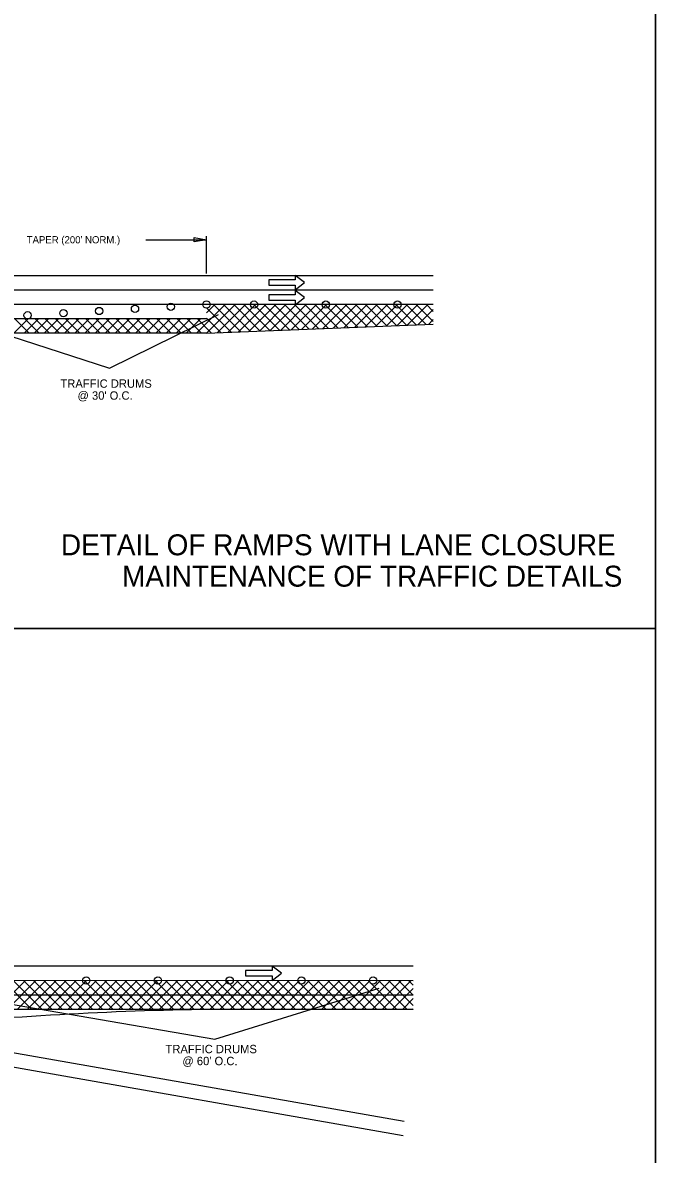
# Model space of a CAD drawing. Extents: x -100 to 745, y -1581 to -107.
# Drawn here: x 292.5 to 345.4, y -1294.6 to -1199.9 of the extents above; entities that cross this region are included whole.
import ezdxf

# ---------------------------------------------------------------- set-up
doc = ezdxf.new("R2010")
doc.units = 0
for name, color, linetype in [('Default', 7, 'Continuous'), ('R_Contour Annot', 7, 'Continuous'), ('R_Draft', 7, 'Continuous'), ('R_Drive', 7, 'Continuous'), ('R_Erosion', 7, 'Continuous'), ('R_Exist Surface', 7, 'Continuous'), ('R_MOT', 7, 'Continuous')]:
    doc.layers.add(name, color=color, linetype=linetype)

msp = doc.modelspace()

# ---------------------------------------------------------------- linework, layer by layer
at = {"layer": 'Default'}
for points in [[(315.278, -1222.246), (316.056, -1221.646), (315.278, -1221.046), (315.278, -1221.421), (313.071, -1221.421), (313.071, -1221.871), (315.278, -1221.871)], [(315.278, -1223.502), (316.056, -1222.902), (315.278, -1222.302), (315.278, -1222.677), (313.071, -1222.677), (313.071, -1223.127), (315.278, -1223.127)], [(313.328, -1280.021), (314.107, -1279.421), (313.328, -1278.821), (313.328, -1279.196), (311.121, -1279.196), (311.121, -1279.646), (313.328, -1279.646)]]:
    msp.add_lwpolyline(points, close=True, dxfattribs=at)
at = {"layer": 'R_Contour Annot'}
for points in [[(175.406, -1140.582), (345.406, -1140.582), (345.406, -1250.582), (175.406, -1250.582)], [(175.406, -1250.582), (345.406, -1250.582), (345.406, -1360.582), (175.406, -1360.582)]]:
    msp.add_lwpolyline(points, close=True, dxfattribs=at)
at = {"layer": 'R_Draft'}
for p, q in [((326.815, -1221.09), (196.834, -1221.09)), ((326.815, -1222.29), (196.834, -1222.29)), ((326.815, -1223.49), (196.834, -1223.49)), ((307.002, -1225.89), (309.404, -1223.488)), ((307.85, -1225.89), (310.252, -1223.488)), ((307.851, -1223.763), (309.896, -1225.808)), ((307.852, -1224.191), (308.555, -1223.488)), ((308.424, -1223.488), (310.712, -1225.776)), ((308.734, -1225.855), (311.101, -1223.488)), ((309.273, -1223.488), (311.528, -1225.743)), ((309.618, -1225.819), (311.949, -1223.488)), ((310.121, -1223.488), (312.344, -1225.71)), ((310.502, -1225.784), (312.797, -1223.489)), ((310.97, -1223.488), (313.159, -1225.678)), ((311.386, -1225.749), (313.646, -1223.489)), ((311.819, -1223.488), (313.975, -1225.645)), ((312.27, -1225.713), (314.494, -1223.489)), ((312.667, -1223.489), (314.791, -1225.612)), ((313.154, -1225.678), (315.343, -1223.489)), ((313.516, -1223.489), (315.607, -1225.58)), ((314.037, -1225.643), (316.191, -1223.489)), ((314.365, -1223.489), (316.423, -1225.547)), ((314.921, -1225.607), (317.04, -1223.489)), ((315.213, -1223.489), (317.239, -1225.515)), ((315.805, -1225.572), (317.888, -1223.489)), ((316.062, -1223.489), (318.055, -1225.482)), ((316.689, -1225.537), (318.737, -1223.489)), ((316.91, -1223.489), (318.871, -1225.449)), ((317.573, -1225.501), (319.585, -1223.489)), ((317.759, -1223.489), (319.687, -1225.417)), ((318.457, -1225.466), (320.433, -1223.489)), ((318.608, -1223.489), (320.502, -1225.384)), ((319.341, -1225.43), (321.282, -1223.489)), ((319.456, -1223.489), (321.318, -1225.351)), ((320.225, -1225.395), (322.13, -1223.489)), ((320.305, -1223.489), (322.134, -1225.319)), ((321.109, -1225.36), (322.979, -1223.49)), ((321.153, -1223.489), (322.95, -1225.286)), ((321.992, -1225.324), (323.827, -1223.49)), ((322.002, -1223.489), (323.766, -1225.253)), ((322.851, -1223.49), (324.582, -1225.221)), ((322.876, -1225.289), (324.676, -1223.49)), ((323.699, -1223.49), (325.398, -1225.188)), ((323.76, -1225.254), (325.524, -1223.49)), ((324.548, -1223.49), (326.214, -1225.156)), ((324.644, -1225.218), (326.373, -1223.49)), ((325.396, -1223.49), (326.815, -1224.908)), ((325.528, -1225.183), (326.815, -1223.896)), ((326.245, -1223.49), (326.815, -1224.06)), ((307.855, -1224.69), (237.745, -1224.69)), ((291.728, -1225.89), (292.928, -1224.69)), ((291.807, -1224.69), (293.007, -1225.89)), ((292.577, -1225.89), (293.777, -1224.69)), ((292.656, -1224.69), (293.856, -1225.89)), ((293.425, -1225.89), (294.625, -1224.69)), ((293.504, -1224.69), (294.704, -1225.89)), ((294.274, -1225.89), (295.474, -1224.69)), ((294.353, -1224.69), (295.553, -1225.89)), ((295.123, -1225.89), (296.323, -1224.69)), ((295.201, -1224.69), (296.401, -1225.89)), ((295.971, -1225.89), (297.171, -1224.69)), ((296.05, -1224.69), (297.25, -1225.89)), ((296.82, -1225.89), (298.02, -1224.69)), ((296.898, -1224.69), (298.098, -1225.89)), ((297.668, -1225.89), (298.868, -1224.69)), ((297.747, -1224.69), (298.947, -1225.89)), ((298.517, -1225.89), (299.717, -1224.69)), ((298.595, -1224.69), (299.795, -1225.89)), ((299.365, -1225.89), (300.565, -1224.69)), ((299.444, -1224.69), (300.644, -1225.89)), ((300.214, -1225.89), (301.414, -1224.69)), ((300.292, -1224.69), (301.492, -1225.89)), ((301.062, -1225.89), (302.262, -1224.69)), ((301.141, -1224.69), (302.341, -1225.89)), ((301.911, -1225.89), (303.111, -1224.69)), ((301.989, -1224.69), (303.189, -1225.89)), ((302.759, -1225.89), (303.959, -1224.69)), ((302.838, -1224.69), (304.038, -1225.89)), ((303.608, -1225.89), (304.808, -1224.69)), ((303.686, -1224.69), (304.886, -1225.89)), ((304.456, -1225.89), (305.656, -1224.69)), ((304.535, -1224.69), (305.735, -1225.89)), ((305.305, -1225.89), (306.505, -1224.69)), ((305.383, -1224.69), (306.583, -1225.89)), ((306.153, -1225.89), (307.353, -1224.69)), ((306.232, -1224.69), (307.432, -1225.89)), ((307.08, -1224.69), (308.264, -1225.874)), ((307.854, -1224.615), (309.08, -1225.841)), ((326.412, -1225.148), (326.815, -1224.745)), ((307.855, -1225.89), (326.815, -1225.132)), ((307.855, -1225.89), (240.841, -1225.89)), ((325.145, -1278.839), (186.576, -1278.836)), ((325.145, -1280.039), (186.576, -1280.036)), ((290.302, -1282.438), (292.709, -1280.031)), ((290.83, -1280.031), (293.238, -1282.438)), ((291.151, -1282.438), (293.558, -1280.031)), ((291.679, -1280.031), (294.086, -1282.438)), ((291.999, -1282.438), (294.406, -1280.032)), ((292.528, -1280.031), (294.935, -1282.438)), ((292.848, -1282.438), (295.254, -1280.032)), ((293.376, -1280.031), (295.783, -1282.438)), ((293.696, -1282.438), (296.103, -1280.032)), ((294.225, -1280.032), (296.632, -1282.438)), ((294.545, -1282.438), (296.951, -1280.032)), ((295.074, -1280.032), (297.48, -1282.438)), ((295.393, -1282.438), (297.799, -1280.032)), ((295.923, -1280.032), (298.329, -1282.438)), ((296.242, -1282.438), (298.648, -1280.033)), ((296.771, -1280.032), (299.177, -1282.438)), ((297.09, -1282.438), (299.496, -1280.033)), ((297.62, -1280.032), (300.026, -1282.438)), ((297.939, -1282.438), (300.344, -1280.033)), ((298.469, -1280.033), (300.875, -1282.438)), ((298.787, -1282.438), (301.192, -1280.033)), ((299.317, -1280.033), (301.723, -1282.438)), ((299.636, -1282.438), (302.041, -1280.033)), ((300.166, -1280.033), (302.572, -1282.438)), ((300.484, -1282.438), (302.889, -1280.034)), ((301.015, -1280.033), (303.42, -1282.438)), ((301.333, -1282.438), (303.737, -1280.034)), ((301.864, -1280.033), (304.269, -1282.438)), ((302.181, -1282.438), (304.586, -1280.034)), ((302.712, -1280.034), (305.117, -1282.438)), ((303.03, -1282.438), (305.434, -1280.034)), ((303.561, -1280.034), (305.966, -1282.438)), ((303.878, -1282.438), (306.282, -1280.034)), ((304.41, -1280.034), (306.814, -1282.438)), ((304.727, -1282.438), (307.131, -1280.035)), ((305.259, -1280.034), (307.663, -1282.438)), ((305.575, -1282.438), (307.979, -1280.035)), ((306.107, -1280.034), (308.511, -1282.439)), ((306.424, -1282.438), (308.827, -1280.035)), ((306.956, -1280.035), (309.36, -1282.439)), ((307.273, -1282.438), (309.676, -1280.035)), ((307.805, -1280.035), (310.209, -1282.439)), ((308.121, -1282.439), (310.524, -1280.035)), ((308.653, -1280.035), (311.057, -1282.439)), ((308.97, -1282.439), (311.372, -1280.036)), ((309.502, -1280.035), (311.906, -1282.439)), ((309.818, -1282.439), (312.221, -1280.036)), ((310.351, -1280.035), (312.754, -1282.439)), ((310.667, -1282.439), (313.069, -1280.036)), ((311.2, -1280.036), (313.603, -1282.439)), ((311.515, -1282.439), (313.917, -1280.036)), ((312.048, -1280.036), (314.451, -1282.439)), ((312.364, -1282.439), (314.766, -1280.036)), ((312.897, -1280.036), (315.3, -1282.439)), ((313.212, -1282.439), (315.614, -1280.037)), ((313.746, -1280.036), (316.148, -1282.439)), ((314.061, -1282.439), (316.462, -1280.037)), ((314.595, -1280.036), (316.997, -1282.439)), ((314.909, -1282.439), (317.311, -1280.037)), ((315.443, -1280.037), (317.845, -1282.439)), ((315.758, -1282.439), (318.159, -1280.037)), ((316.292, -1280.037), (318.694, -1282.439)), ((316.606, -1282.439), (319.007, -1280.037)), ((317.141, -1280.037), (319.543, -1282.439)), ((317.455, -1282.439), (319.856, -1280.038)), ((317.99, -1280.037), (320.391, -1282.439)), ((318.303, -1282.439), (320.704, -1280.038)), ((318.838, -1280.037), (321.24, -1282.439)), ((319.152, -1282.439), (321.552, -1280.038)), ((319.687, -1280.038), (322.088, -1282.439)), ((320, -1282.439), (322.401, -1280.038)), ((320.536, -1280.038), (322.937, -1282.439)), ((320.849, -1282.439), (323.249, -1280.038)), ((321.384, -1280.038), (323.785, -1282.439)), ((321.697, -1282.439), (324.097, -1280.039)), ((322.233, -1280.038), (324.634, -1282.439)), ((322.546, -1282.439), (324.946, -1280.039)), ((323.082, -1280.038), (325.145, -1282.102)), ((323.394, -1282.439), (325.145, -1280.688)), ((323.931, -1280.039), (325.145, -1281.253)), ((324.779, -1280.039), (325.145, -1280.405)), ((325.145, -1281.239), (186.576, -1281.236)), ((324.243, -1282.439), (325.145, -1281.536)), ((325.145, -1282.439), (272.284, -1282.438)), ((325.091, -1282.439), (325.145, -1282.385)), ((324.381, -1291.805), (272.254, -1282.668)), ((324.303, -1293.01), (282.706, -1285.718))]:
    msp.add_line(p, q, dxfattribs=at)
for points in [[(175.406, -1140.582), (175.406, -1250.582), (345.406, -1250.582), (345.406, -1140.582)], [(175.406, -1250.582), (175.406, -1360.582), (345.406, -1360.582), (345.406, -1250.582)]]:
    msp.add_lwpolyline(points, close=True, dxfattribs=at)
msp.add_arc((312.956, -1594.665), 312.263, 90.87748, 95.50625, dxfattribs=at)
at = {"layer": 'R_Drive'}
for points in [[(289.291, -1225.429), (299.718, -1228.815), (308.842, -1224.33)], [(285.8, -1281.023), (308.539, -1284.925), (322.287, -1280.659)]]:
    msp.add_lwpolyline(points, dxfattribs=at)
at = {"layer": 'R_Erosion'}
for centre in [(295.871, -1224.207), (298.866, -1224.027), (301.86, -1223.847), (304.855, -1223.668), (307.849, -1223.488), (311.825, -1223.489), (317.825, -1223.489), (323.825, -1223.489), (292.876, -1224.386), (297.783, -1280.023), (303.783, -1280.023), (309.783, -1280.023), (315.783, -1280.023), (321.783, -1280.023)]:
    msp.add_circle(centre, 0.305, dxfattribs=at)
at = {"layer": 'R_Exist Surface'}
for p, q in [((302.778, -1218.065), (307.855, -1218.065)), ((307.855, -1220.89), (307.855, -1217.765))]:
    msp.add_line(p, q, dxfattribs=at)
msp.add_lwpolyline([(306.805, -1217.878), (307.855, -1218.065), (306.805, -1218.253)], close=True, dxfattribs=at)

# ---------------------------------------------------------------- texts
at = {"layer": 'R_Drive'}
for s, p in [('TRAFFIC DRUMS', (295.624, -1230.446)), ("@ 30' O.C.", (297.052, -1231.446)), ('TRAFFIC DRUMS', (304.416, -1286.108)), ("@ 60' O.C.", (305.827, -1287.108))]:
    msp.add_text(s, height=0.7, rotation=360, dxfattribs=at).set_placement(p)
at = {"layer": 'R_Exist Surface'}
msp.add_text("TAPER (200' NORM.)", height=0.6, dxfattribs=at).set_placement((292.8, -1218.365))
at = {"layer": 'R_MOT'}
for s, p in [('DETAIL OF RAMPS WITH LANE CLOSURE', (295.663, -1244.457)), ('MAINTENANCE OF TRAFFIC DETAILS', (300.779, -1247.082))]:
    msp.add_text(s, height=1.75, dxfattribs=at).set_placement(p)

doc.saveas('drawing.dxf')
